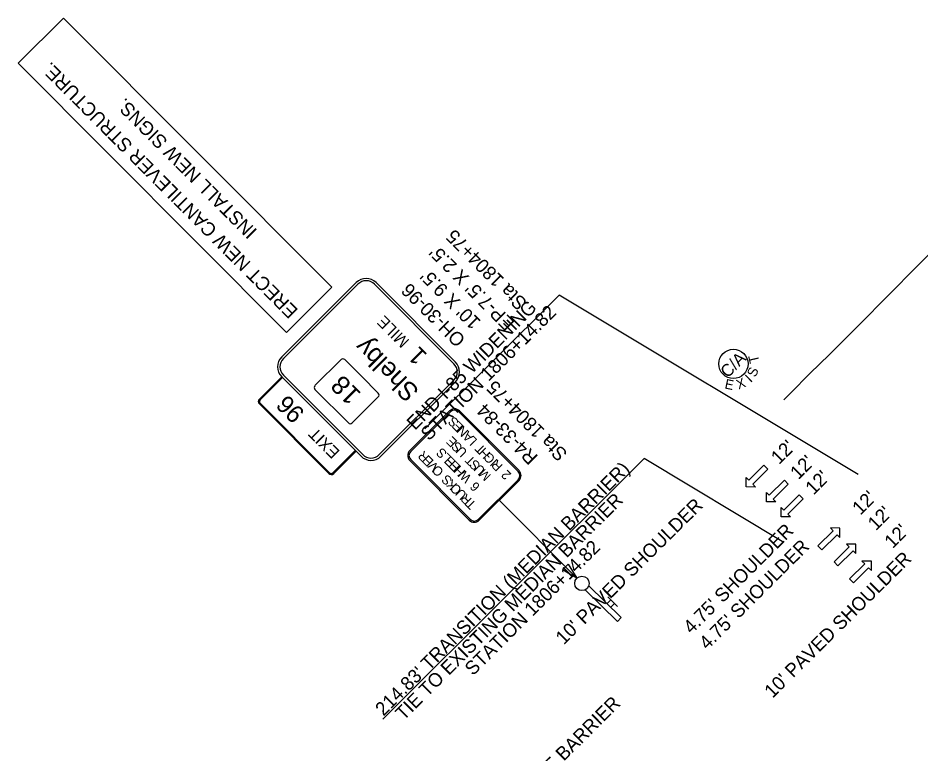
# Model space of a CAD drawing. Extents: x 1825735 to 1827318, y 1193725 to 1195507.
# Drawn here: x 1826114.4 to 1826577.4, y 1194401.7 to 1194779.1 of the extents above; entities that cross this region are included whole.
import ezdxf

# ---------------------------------------------------------------- set-up
doc = ezdxf.new("R2010")
doc.units = 0
for name, color, linetype in [('RD_EX_Road', 7, 'Continuous'), ('RD_PD_Final_LnLine', 7, 'Continuous'), ('RD_PD_Final_TX', 7, 'Continuous'), ('RD_Sketch8', 7, 'Continuous'), ('SN_P_Signs', 7, 'Continuous')]:
    doc.layers.add(name, color=color, linetype=linetype)

# ---------------------------------------------------------------- blocks, each defined once
blk = doc.blocks.new('SARRW2')
at = {"layer": 'RD_PD_Final_LnLine'}
blk.add_lwpolyline([(-12, 1.2), (-12, -1.2), (-2.83, -1.2), (-2.83, -2.83), (0, 0), (-2.83, 2.83), (-2.83, 1.2)], close=True, dxfattribs=at)

msp = doc.modelspace()

# ---------------------------------------------------------------- linework, layer by layer
at = {"layer": 'RD_EX_Road'}
msp.add_lwpolyline([(1826590.21, 1194666.65), (1826575.67, 1194651.98), (1826560.45, 1194636.69), (1826545.89, 1194621.99), (1826530.44, 1194606.54), (1826520.45, 1194596.85), (1826510.7, 1194586.85), (1826507.08, 1194583.24)], dxfattribs=at)
at = {"layer": 'RD_PD_Final_TX'}
for p, q in [((1826391.84, 1194637.02), (1826323.05, 1194568.45)), ((1826545.2, 1194545.06), (1826391.84, 1194637.02)), ((1826435.49, 1194553.15), (1826301.4, 1194419.48)), ((1826507.12, 1194510.19), (1826435.49, 1194553.15))]:
    msp.add_line(p, q, dxfattribs=at)
at = {"layer": 'RD_Sketch8'}
msp.add_circle((1826481.23, 1194601.71), 7.5, dxfattribs=at)
at = {"layer": 'SN_P_Signs'}
for p, q in [((1826114.39, 1194755.93), (1826137.62, 1194779.1)), ((1826137.62, 1194779.1), (1826275.32, 1194641.02)), ((1826252.09, 1194617.86), (1826114.39, 1194755.93)), ((1826275.32, 1194641.02), (1826252.09, 1194617.86)), ((1826266.67, 1194590.55), (1826280.06, 1194603.9)), ((1826281.96, 1194603.89), (1826290.45, 1194595.39)), ((1826238.13, 1194583.7), (1826249.61, 1194595.14)), ((1826249.61, 1194595.14), (1826250.03, 1194594.71)), ((1826290.45, 1194595.39), (1826299.12, 1194586.69)), ((1826283.83, 1194571.43), (1826266.67, 1194588.64)), ((1826238.56, 1194581.58), (1826274.14, 1194545.89)), ((1826299.12, 1194584.78), (1826285.74, 1194571.43)), ((1826273.72, 1194545.47), (1826238.13, 1194581.15)), ((1826275.84, 1194545.89), (1826287.31, 1194557.33)), ((1826287.74, 1194556.9), (1826276.27, 1194545.46)), ((1826287.31, 1194557.33), (1826287.74, 1194556.9)), ((1826361.11, 1194531.74), (1826400.95, 1194491.77)), ((1826416.49, 1194478.76), (1826418.42, 1194480.73)), ((1826416.92, 1194482.19), (1826421.88, 1194477.32)), ((1826418.4, 1194476.88), (1826420.34, 1194478.87))]:
    msp.add_line(p, q, dxfattribs=at)
for points in [[(1826249.62, 1194605.32), (1826287.86, 1194643.45)], [(1826250.47, 1194604.47), (1826288.7, 1194642.6)], [(1826297.19, 1194642.59), (1826337.86, 1194601.8)], [(1826298.04, 1194643.44), (1826338.71, 1194602.65)], [(1826291.13, 1194555.2), (1826250.46, 1194595.99)], [(1826250.03, 1194594.71), (1826238.56, 1194583.27)], [(1826290.28, 1194554.35), (1826249.61, 1194595.14)], [(1826337.85, 1194593.32), (1826299.61, 1194555.19)], [(1826338.7, 1194592.47), (1826300.46, 1194554.34)], [(1826335.73, 1194577.6), (1826315.33, 1194557.27)], [(1826336.15, 1194577.17), (1826315.76, 1194556.84)], [(1826370.89, 1194546.57), (1826340.4, 1194577.17)], [(1826371.32, 1194547), (1826340.82, 1194577.59)], [(1826315.32, 1194552.18), (1826345.82, 1194521.58)], [(1826315.75, 1194552.6), (1826346.25, 1194522)], [(1826350.49, 1194522), (1826370.89, 1194542.33)], [(1826350.91, 1194521.57), (1826371.31, 1194541.9)], [(1826405.27, 1194485.84), (1826421.79, 1194469.65), (1826423.74, 1194471.64), (1826407.09, 1194487.97)]]:
    msp.add_lwpolyline(points, dxfattribs=at)
msp.add_lwpolyline([(1826396.5, 1194498.95), (1826400.92, 1194491.74), (1826393.63, 1194496.02)], close=True, dxfattribs=at)
msp.add_circle((1826403.57, 1194489.14), 3.71, dxfattribs=at)
for centre, radius, start, end in [((1826292.94, 1194638.35), 7.2, 44.9205, 134.9205), ((1826292.94, 1194638.35), 6, 44.9205, 134.9205), ((1826254.7, 1194600.22), 7.2, 134.9205, 224.9205), ((1826254.7, 1194600.22), 6, 134.9205, 224.9205), ((1826281.01, 1194602.94), 1.35, 44.9226, 134.9226), ((1826333.61, 1194597.57), 6, 314.9205, 44.9205), ((1826333.61, 1194597.57), 7.2, 314.9205, 44.9205), ((1826267.63, 1194589.59), 1.35, 134.9205, 224.9205), ((1826298.17, 1194585.73), 1.35, 314.9226, 44.9226), ((1826239.41, 1194582.42), 1.8, 134.9205, 224.9205), ((1826239.41, 1194582.42), 1.2, 134.9205, 224.9205), ((1826338.27, 1194575.05), 3.6, 44.9091, 134.9091), ((1826338.27, 1194575.05), 3, 44.9091, 134.9091), ((1826284.78, 1194572.39), 1.35, 224.9205, 314.9226), ((1826295.38, 1194559.44), 7.2, 224.9205, 314.9205), ((1826295.38, 1194559.44), 6, 224.9205, 314.9205), ((1826317.87, 1194554.72), 3.6, 134.9091, 224.9091), ((1826317.87, 1194554.72), 3, 134.9091, 224.9091), ((1826274.99, 1194546.74), 1.8, 224.9205, 314.9205), ((1826274.99, 1194546.74), 1.2, 224.9205, 314.9205), ((1826368.77, 1194544.45), 3, 314.9091, 44.9091), ((1826368.77, 1194544.45), 3.6, 314.9091, 44.9091), ((1826348.37, 1194524.12), 3.6, 224.9091, 314.9091), ((1826348.37, 1194524.12), 3, 224.9091, 314.9091)]:
    msp.add_arc(centre, radius, start, end, dxfattribs=at)

# ---------------------------------------------------------------- block references
at = {"layer": 'RD_PD_Final_LnLine', "xscale": 1.2000000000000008}
for p, yscale, rotation in [((1826487.75, 1194538.58), -1.2000000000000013, -135.0673694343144), ((1826498.19, 1194530.94), -1.2000000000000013, -135.0673694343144), ((1826505.8, 1194523.31), -1.2000000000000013, -135.0673694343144), ((1826535.84, 1194517.54), 1.200000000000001, 44.88558225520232), ((1826544.06, 1194509.29), 1.200000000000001, 44.88558225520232), ((1826551.99, 1194500.6), 1.200000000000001, 44.88558225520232)]:
    msp.add_blockref('SARRW2', p, dxfattribs=dict(at, yscale=yscale, rotation=rotation))

# ---------------------------------------------------------------- texts
at = {"layer": 'RD_PD_Final_TX'}
for s, rotation, p in [('END I-85 WIDENING ', 44.9091, (1826317.93, 1194567.3)), ('STATION 1806+14.82', 44.9091, (1826325.13, 1194561.95)), ("12'", 44.726, (1826504.69, 1194549.8)), ("12'", 44.726, (1826514.55, 1194542.01)), ("214.83' TRANSITION (MEDIAN BARRIER)", 44.9091, (1826301.78, 1194420.74)), ("12'", 44.726, (1826522.35, 1194534.19)), ("12'", 45.0922, (1826546.42, 1194523.8)), ('TIE TO EXISTING MEDIAN BARRIER', 44.9091, (1826312.1, 1194418.5)), ("10' PAVED SHOULDER", 44.76, (1826394.27, 1194457.31)), ("12'", 45.0922, (1826554.35, 1194515.84)), ("4.75' SHOULDER", 44.9091, (1826459.73, 1194462.86)), ("12'", 45.0922, (1826562.92, 1194506.66)), ('STATION 1806+14.82', 44.9091, (1826347.69, 1194441.44)), ("4.75' SHOULDER", 44.9091, (1826467.83, 1194454.74)), ("10' PAVED SHOULDER", 44.76, (1826501.32, 1194429.94)), ("2.5' CONCRETE BARRIER", 44.76, (1826342.79, 1194346.61))]:
    msp.add_text(s, height=7, rotation=rotation, dxfattribs=at).set_placement(p)
at = {"layer": 'RD_Sketch8'}
for s, height, rotation, p in [('C/A', 6.25, 44.9091, (1826478.3, 1194594.16)), ('T', 5, 103.0943, (1826494.6, 1194602.74)), ('I', 5, 44.7097, (1826490.12, 1194591.86)), ('S', 5, 66.7015, (1826492.58, 1194594.57)), ('E', 5, 348.1204, (1826476.48, 1194589.17)), ('X', 5, 20.5497, (1826483.85, 1194588.54))]:
    msp.add_text(s, height=height, rotation=rotation, dxfattribs=at).set_placement(p)
at = {"layer": 'SN_P_Signs'}
for s, height, rotation, p in [('ERECT NEW CANTILEVER STRUCTURE.', 7, 134.9206, (1826258.41, 1194629.29)), ('INSTALL NEW SIGNS.', 7, 134.9206, (1826237.43, 1194670.15)), ('Sta 1804+75', 7, 134.9206, (1826375.86, 1194633.48)), ("EP-7.5' X 2.5'", 7, 134.9206, (1826369.5, 1194623.01)), ("10' X 9.5'", 7, 134.9206, (1826352.08, 1194623.62)), ('OH-30-96', 7, 134.9206, (1826344.28, 1194614.59)), ('MILE', 6, 134.9205, (1826315.44, 1194613.67)), ('Shelby', 9.6, 134.9205, (1826320.62, 1194588.09)), ('1', 9, 134.9205, (1826324.71, 1194606.5)), ('18', 9.6, 134.9205, (1826290.83, 1194586.5)), ('Sta 1804+75', 7, 134.9092, (1826396.61, 1194556.01)), ('96', 9, 134.9205, (1826261.88, 1194576.88)), ('R4-33-84', 7, 134.9092, (1826381.49, 1194554.32)), ('S', 4.8, 134.9091, (1826340.84, 1194572.05)), ('E', 4.8, 134.9091, (1826343.11, 1194569.77)), ('EXIT', 6, 134.9205, (1826279.76, 1194556.83)), ('N', 4.8, 134.9091, (1826345.67, 1194567.2)), ('E', 4.8, 134.9091, (1826339.99, 1194561.85)), ('A', 4.8, 134.9091, (1826348.36, 1194564.5)), ('L', 4.8, 134.9091, (1826350.25, 1194562.61)), ('S', 4.8, 134.9091, (1826334.75, 1194556.06)), ('S', 4.8, 134.9091, (1826342.56, 1194559.27)), ('U', 4.8, 134.9091, (1826345.13, 1194556.7)), ('T', 4.8, 134.9091, (1826354.48, 1194558.36)), ('H', 4.8, 134.9091, (1826356.91, 1194555.93)), ('R', 4.8, 134.9091, (1826325.62, 1194554.17)), ('E', 4.8, 134.9091, (1826327.89, 1194551.9)), ('L', 4.8, 134.9091, (1826337.01, 1194553.79)), ('E', 4.8, 134.9091, (1826339.28, 1194551.51)), ('T', 4.8, 134.9091, (1826349.36, 1194552.45)), ('G', 4.8, 134.9091, (1826359.48, 1194553.35)), ('V', 4.8, 134.9091, (1826330.52, 1194549.25)), ('O', 4.8, 134.9091, (1826333.06, 1194546.71)), ('E', 4.8, 134.9091, (1826341.55, 1194549.24)), ('H', 4.8, 134.9091, (1826344.11, 1194546.67)), ('S', 4.8, 134.9091, (1826351.79, 1194550.01)), ('U', 4.8, 134.9091, (1826354.36, 1194547.44)), ('I', 4.8, 134.9091, (1826360.67, 1194552.16)), ('R', 4.8, 134.9091, (1826363.23, 1194549.58)), ('S', 4.8, 134.9091, (1826337.45, 1194542.3)), ('W', 4.8, 134.9091, (1826347.23, 1194543.54)), ('M', 4.8, 134.9091, (1826357.27, 1194544.52)), ('2', 4.8, 134.9091, (1826367.63, 1194545.17)), ('K', 4.8, 134.9091, (1826339.88, 1194539.87)), ('C', 4.8, 134.9091, (1826342.3, 1194537.44)), ('6', 4.8, 134.9091, (1826351.62, 1194539.13)), ('U', 4.8, 134.9091, (1826344.87, 1194534.86)), ('R', 4.8, 134.9091, (1826347.44, 1194532.29)), ('T', 4.8, 134.9091, (1826349.7, 1194530.01))]:
    msp.add_text(s, height=height, rotation=rotation, dxfattribs=at).set_placement(p)

doc.saveas('drawing.dxf')
